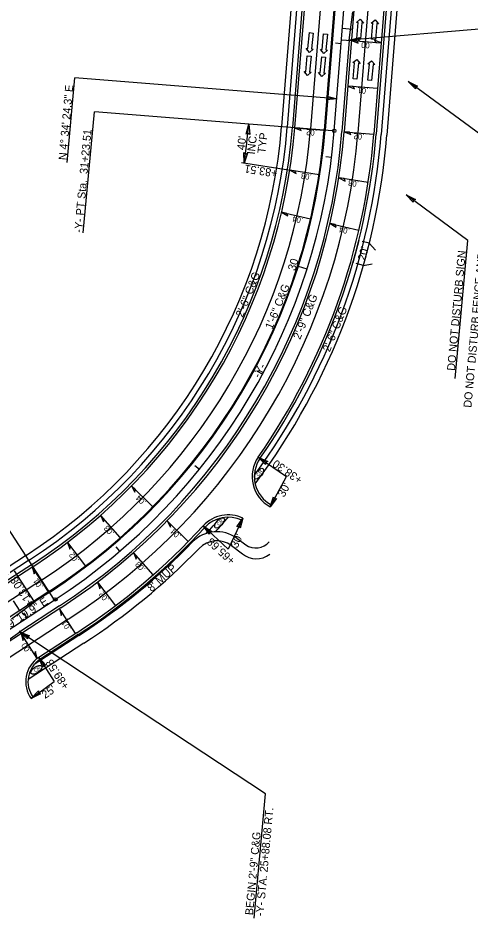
# Model space of a CAD drawing. Extents: x 2010838 to 2015151, y 441905 to 447792.
# Drawn here: x 2012349 to 2012745, y 445665 to 446452 of the extents above; entities that cross this region are included whole.
import ezdxf

# ---------------------------------------------------------------- set-up
doc = ezdxf.new("R2010")
doc.units = 0
for name, color, linetype in [('A-Wall-Abov', 7, 'Continuous'), ('A-Wall-Blow', 7, 'Continuous'), ('A-Wall-Comp', 7, 'Continuous'), ('B-Sheet Number', 7, 'Continuous'), ('C-Building', 7, 'Continuous'), ('C-EOP 1', 7, 'Continuous'), ('C-Grave Plots', 7, 'Continuous'), ('C-Profile', 7, 'Continuous'), ('C-SHBD-TEXT', 7, 'Continuous'), ('CLRD', 7, 'Continuous'), ('Cont-2-Lidar', 7, 'Continuous'), ('DEED', 7, 'Continuous'), ('Default_10ft_LIDAR_Contou', 7, 'Continuous'), ('Default_2FT_LIDAR_Contour', 7, 'Continuous'), ('HATCH', 7, 'Continuous'), ('s-Existing Major', 7, 'Continuous'), ('S-Existing Minor', 7, 'Continuous'), ('S-overhead electric', 7, 'Continuous'), ('TEXT-LG', 7, 'Continuous'), ('TEXT-MED', 7, 'Continuous'), ('X2', 7, 'Continuous'), ('X4', 7, 'Continuous')]:
    doc.layers.add(name, color=color, linetype=linetype)

msp = doc.modelspace()

# ---------------------------------------------------------------- linework, layer by layer
at = {"layer": 'A-Wall-Abov'}
for p, q in [((2012645.07, 446448.16), (2012648.42, 446451.05)), ((2012648.42, 446451.05), (2012651.35, 446447.64)), ((2012658.07, 446447.62), (2012661.42, 446450.5)), ((2012661.42, 446450.5), (2012664.35, 446447.09)), ((2012646.56, 446448.04), (2012645.07, 446448.16)), ((2012645.41, 446434.09), (2012646.56, 446448.04)), ((2012649.85, 446447.77), (2012648.69, 446433.82)), ((2012651.35, 446447.64), (2012649.85, 446447.77)), ((2012659.57, 446447.49), (2012658.07, 446447.62)), ((2012658.41, 446433.54), (2012659.57, 446447.49)), ((2012662.86, 446447.22), (2012661.7, 446433.27)), ((2012664.35, 446447.09), (2012662.86, 446447.22)), ((2012602.65, 446425.34), (2012603.97, 446439.28)), ((2012603.97, 446439.28), (2012607.25, 446438.97)), ((2012607.25, 446438.97), (2012605.93, 446425.03)), ((2012615.15, 446424.44), (2012616.47, 446438.38)), ((2012616.47, 446438.38), (2012619.75, 446438.07)), ((2012619.75, 446438.07), (2012618.43, 446424.13)), ((2012648.69, 446433.82), (2012645.41, 446434.09)), ((2012661.7, 446433.27), (2012658.41, 446433.54)), ((2012600.8, 446405.03), (2012602.13, 446418.97)), ((2012604.04, 446422.05), (2012601.15, 446425.48)), ((2012601.15, 446425.48), (2012602.65, 446425.34)), ((2012602.13, 446418.97), (2012605.41, 446418.66)), ((2012607.43, 446424.89), (2012604.04, 446422.05)), ((2012605.41, 446418.66), (2012604.09, 446404.72)), ((2012605.93, 446425.03), (2012607.43, 446424.89)), ((2012616.54, 446421.15), (2012613.65, 446424.59)), ((2012613.65, 446424.59), (2012615.15, 446424.44)), ((2012619.92, 446423.99), (2012616.54, 446421.15)), ((2012618.43, 446424.13), (2012619.92, 446423.99)), ((2012613.42, 446404.18), (2012614.74, 446418.12)), ((2012614.74, 446418.12), (2012618.03, 446417.81)), ((2012618.03, 446417.81), (2012616.71, 446403.87)), ((2012642.07, 446413.04), (2012645.45, 446415.88)), ((2012643.56, 446412.9), (2012642.07, 446413.04)), ((2012642.24, 446398.96), (2012643.56, 446412.9)), ((2012645.45, 446415.88), (2012648.34, 446412.44)), ((2012646.85, 446412.58), (2012645.53, 446398.65)), ((2012648.34, 446412.44), (2012646.85, 446412.58)), ((2012654.99, 446411.93), (2012658.37, 446414.77)), ((2012656.48, 446411.79), (2012654.99, 446411.93)), ((2012655.16, 446397.85), (2012656.48, 446411.79)), ((2012658.37, 446414.77), (2012661.26, 446411.34)), ((2012659.77, 446411.48), (2012658.45, 446397.54)), ((2012661.26, 446411.34), (2012659.77, 446411.48)), ((2012602.2, 446401.73), (2012599.31, 446405.17)), ((2012599.31, 446405.17), (2012600.8, 446405.03)), ((2012605.58, 446404.58), (2012602.2, 446401.73)), ((2012604.09, 446404.72), (2012605.58, 446404.58)), ((2012614.82, 446400.88), (2012611.93, 446404.32)), ((2012611.93, 446404.32), (2012613.42, 446404.18)), ((2012618.2, 446403.73), (2012614.82, 446400.88)), ((2012616.71, 446403.87), (2012618.2, 446403.73)), ((2012645.53, 446398.65), (2012642.24, 446398.96)), ((2012658.45, 446397.54), (2012655.16, 446397.85))]:
    msp.add_line(p, q, dxfattribs=at)
at = {"layer": 'A-Wall-Blow'}
for p, q in [((2012640.84, 446432.42), (2012666.76, 446430.34)), ((2012663.57, 446390.47), (2012637.65, 446392.54)), ((2012591.1, 446356.14), (2012617.02, 446354.07)), ((2012634.47, 446352.67), (2012660.38, 446350.6)), ((2012612.43, 446314.99), (2012586.74, 446318.98)), ((2012655.42, 446308.32), (2012629.73, 446312.31)), ((2012579.64, 446282.24), (2012604.97, 446276.36)), ((2012622.02, 446272.41), (2012647.34, 446266.53)), ((2012448.4, 446042.87), (2012466.98, 446024.68)), ((2012438.42, 445997.61), (2012421.25, 446017.13)), ((2012479.48, 446012.43), (2012498.05, 445994.24)), ((2012392.26, 445993.47), (2012407.95, 445972.73)), ((2012467.16, 445964.96), (2012449.98, 445984.47)), ((2012375.69, 445950.16), (2012361.53, 445971.97)), ((2012418.5, 445958.77), (2012434.19, 445938.04)), ((2012399.36, 445913.73), (2012385.23, 445935.49)), ((2012365.87, 445891.86), (2012351.68, 445913.7))]:
    msp.add_line(p, q, dxfattribs=at)
at = {"layer": 'A-Wall-Comp'}
for points in [[(2012640.84, 446432.42), (2012646.67, 446429.94), (2012645.45, 446432.05)], [(2012666.76, 446430.34), (2012660.94, 446432.81), (2012662.15, 446430.71)], [(2012637.65, 446392.54), (2012643.48, 446390.07), (2012642.27, 446392.17)], [(2012591.1, 446356.14), (2012596.93, 446353.67), (2012595.71, 446355.77)], [(2012634.47, 446352.67), (2012640.29, 446350.2), (2012639.08, 446352.3)], [(2012586.74, 446318.98), (2012592.36, 446316.08), (2012591.31, 446318.27)], [(2012629.73, 446312.31), (2012635.35, 446309.41), (2012634.3, 446311.6)], [(2012579.64, 446282.24), (2012585.03, 446278.94), (2012584.15, 446281.19)], [(2012622.02, 446272.41), (2012627.41, 446269.1), (2012626.52, 446271.36)], [(2012448.4, 446042.87), (2012451.29, 446037.24), (2012451.71, 446039.64)], [(2012421.25, 446017.13), (2012423.71, 446011.3), (2012424.3, 446013.66)], [(2012479.48, 446012.43), (2012482.36, 446006.81), (2012482.78, 446009.2)], [(2012392.26, 445993.47), (2012394.29, 445987.48), (2012395.05, 445989.78)], [(2012449.98, 445984.47), (2012452.45, 445978.65), (2012453.04, 445981)], [(2012361.53, 445971.97), (2012363.12, 445965.84), (2012364.05, 445968.09)], [(2012418.5, 445958.77), (2012420.53, 445952.78), (2012421.29, 445955.09)], [(2012385.23, 445935.49), (2012386.82, 445929.37), (2012387.75, 445931.61)], [(2012351.68, 445913.7), (2012353.28, 445907.57), (2012354.2, 445909.82)], [(2012365.87, 445891.86), (2012364.28, 445897.98), (2012363.35, 445895.73)]]:
    msp.add_lwpolyline(points, close=True, dxfattribs=at)
at = {"layer": 'B-Sheet Number'}
for p, q in [((2012656.42, 446255.07), (2012650.05, 446256.65)), ((2012651.2, 446235.53), (2012644.89, 446237.33))]:
    msp.add_line(p, q, dxfattribs=at)
at = {"layer": 'C-Building'}
for p, q in [((2012631.84, 446429.61), (2012626.86, 446430.01)), ((2012623.36, 446329.98), (2012618.4, 446330.6)), ((2012562.97, 446140.51), (2012558.57, 446142.88)), ((2012507.72, 446057.33), (2012503.83, 446060.47)), ((2012438.1, 445985.75), (2012434.85, 445989.55)), ((2012356.91, 445927.53), (2012354.19, 445931.72))]:
    msp.add_line(p, q, dxfattribs=at)
at = {"layer": 'C-EOP 1'}
msp.add_line((2012601.96, 446232.44), (2012594.34, 446234.87), dxfattribs=at)
at = {"layer": 'C-Profile'}
for p, q in [((2012638.85, 446432.58), (2012642.09, 446457.4)), ((2012638.85, 446432.58), (2012632.47, 446352.83)), ((2012343.24, 445926.69), (2012363.52, 445941.36)), ((2012385.33, 445937.94), (2012350.6, 445915.37)), ((2012330.31, 445900.7), (2012350.6, 445915.37))]:
    msp.add_line(p, q, dxfattribs=at)
msp.add_arc((2012087.46, 446396.43), 546.75, 303.01114, 355.42659, dxfattribs=at)
at = {"layer": 'C-SHBD-TEXT'}
for p, q in [((2012632.92, 446443.08), (2012641.64, 446442.38)), ((2012632.12, 446433.11), (2012640.84, 446432.42)), ((2012350.94, 445933.19), (2012344.95, 445942.41)), ((2012356.18, 445906.78), (2012350.19, 445916))]:
    msp.add_line(p, q, dxfattribs=at)
at = {"layer": 'CLRD'}
for p, q in [((2012625.74, 446353.37), (2012648.26, 446634.86)), ((2012312.18, 445898.46), (2012381.66, 445943.6))]:
    msp.add_line(p, q, dxfattribs=at)
msp.add_arc((2012087.46, 446396.43), 540, 303.01114, 355.42659, dxfattribs=at)
at = {"layer": 'DEED'}
for p, q in [((2012636.91, 446593.31), (2012617.77, 446354.01)), ((2012377.3, 445950.31), (2012363.52, 445941.36))]:
    msp.add_line(p, q, dxfattribs=at)
msp.add_arc((2012087.46, 446396.43), 532, 303.01114, 355.42659, dxfattribs=at)
at = {"layer": 'Default_10ft_LIDAR_Contou'}
for p, q in [((2012392.06, 446325.83), (2012398.87, 446399.86)), ((2012628, 446381.53), (2012398.87, 446399.86)), ((2012406.15, 446264.23), (2012415.89, 446370.16)), ((2012624.25, 446353.49), (2012415.89, 446370.16)), ((2012380.73, 445943.63), (2012253.57, 446139.34))]:
    msp.add_line(p, q, dxfattribs=at)
for centre in [(2012625.74, 446353.37), (2012625.74, 446353.37), (2012381.66, 445943.6), (2012381.66, 445943.6)]:
    msp.add_circle(centre, 1.5, dxfattribs=at)
at = {"layer": 'HATCH'}
for p, q in [((2012627.58, 446636.51), (2012605.06, 446355.02)), ((2012668.94, 446633.2), (2012646.43, 446351.71)), ((2012370.35, 445961), (2012300.87, 445915.86)), ((2012392.96, 445926.2), (2012323.48, 445881.06))]:
    msp.add_line(p, q, dxfattribs=at)
for radius in [519.25, 560.75]:
    msp.add_arc((2012087.46, 446396.43), radius, 303.01114, 355.42659, dxfattribs=at)
at = {"layer": 's-Existing Major'}
for points in [[(2012647.95, 446431.81), (2012638.85, 446432.58), (2012647.73, 446434.95), (2012646.72, 446433.26)], [(2012696.8, 446390.03), (2012690.47, 446396.61), (2012698.71, 446392.54), (2012696.84, 446391.93)], [(2012619.15, 446383.79), (2012628, 446381.53), (2012618.85, 446380.66), (2012620.12, 446382.16)], [(2012548.6, 446350.51), (2012550.86, 446359.36), (2012551.73, 446350.21), (2012550.23, 446351.48)], [(2012549.76, 446333.82), (2012546.85, 446325.17), (2012546.65, 446334.35), (2012548.06, 446332.97)], [(2012694.88, 446290.93), (2012688.56, 446297.53), (2012696.79, 446293.44), (2012694.91, 446292.83)], [(2012565.72, 446061.71), (2012559.22, 446068.12), (2012567.56, 446064.26), (2012565.7, 446063.61)], [(2012575.32, 446031.73), (2012569.71, 446024.52), (2012572.56, 446033.25), (2012573.43, 446031.49)], [(2012540.62, 446007.2), (2012545.86, 446014.67), (2012543.44, 446005.81), (2012542.49, 446007.53)], [(2012516.52, 446000.61), (2012510.94, 446007.83), (2012518.69, 446002.89), (2012516.76, 446002.49)], [(2012357.25, 445909.12), (2012350.6, 445915.37), (2012359.03, 445911.72), (2012357.19, 445911.02)], [(2012370.71, 445884.32), (2012367.1, 445892.71), (2012373.38, 445885.99), (2012371.41, 445886.08)], [(2012368.74, 445861.02), (2012360.57, 445856.94), (2012366.92, 445863.59), (2012366.94, 445861.62)]]:
    msp.add_lwpolyline(points, close=True, dxfattribs=at)
at = {"layer": 'S-Existing Minor'}
for p, q in [((2012849.28, 446450.8), (2012638.85, 446432.58)), ((2012767.58, 446339.91), (2012690.47, 446396.61)), ((2012585.69, 446319.14), (2012544.71, 446325.5)), ((2012742.63, 446257.55), (2012688.56, 446297.53)), ((2012731.53, 446136.8), (2012742.63, 446257.55)), ((2012559.22, 446068.12), (2012583.84, 446050.98)), ((2012569.71, 446024.52), (2012583.84, 446050.98)), ((2012545.86, 446014.67), (2012533.04, 445987.55)), ((2012510.94, 446007.83), (2012533.04, 445987.55)), ((2012363.52, 445941.36), (2012345.92, 445968.45)), ((2012565.55, 445773.54), (2012350.6, 445915.37)), ((2012367.1, 445892.71), (2012380.72, 445871.74)), ((2012360.57, 445856.94), (2012380.72, 445871.74)), ((2012555.57, 445664.94), (2012565.55, 445773.54))]:
    msp.add_line(p, q, dxfattribs=at)
msp.add_arc((2012087.46, 446396.43), 464.88, 351.18238, 355.42659, dxfattribs=at)
at = {"layer": 'S-overhead electric'}
for p, q in [((2012682.9, 446632.09), (2012660.38, 446350.6)), ((2012611.86, 446615.65), (2012591.1, 446356.14)), ((2012636.16, 446593.37), (2012617.02, 446354.07)), ((2012649.62, 446542.13), (2012634.47, 446352.67)), ((2012656.42, 446255.07), (2012661.88, 446249.18)), ((2012651.2, 446235.53), (2012658.83, 446236.95)), ((2012362.72, 445972.74), (2012293.25, 445927.6)), ((2012376.89, 445950.94), (2012307.41, 445905.8)), ((2012386.42, 445936.26), (2012316.95, 445891.13)), ((2012400.59, 445914.46), (2012367.1, 445892.71))]:
    msp.add_line(p, q, dxfattribs=at)
for centre, radius, start, end in [((2012087.46, 446396.43), 505.25, 303.01114, 355.42659), ((2012087.46, 446396.43), 531.25, 303.01114, 355.42659), ((2012087.46, 446396.43), 548.75, 303.01114, 355.42659), ((2012087.46, 446396.43), 574.75, 325.16479, 355.42659), ((2012583.84, 446050.98), 30, 145.16479, 241.9049), ((2012533.04, 445987.55), 30, 64.70104, 137.45962), ((2012087.46, 446396.43), 574.75, 303.01114, 317.45962), ((2012380.72, 445871.74), 25, 123.01114, 216.29419)]:
    msp.add_arc(centre, radius, start, end, dxfattribs=at)
at = {"layer": 'TEXT-LG'}
for p, q in [((2012601.76, 446633.53), (2012579.64, 446357.06)), ((2012689.38, 446631.57), (2012666.86, 446350.08)), ((2012694.36, 446631.17), (2012671.85, 446349.68)), ((2012606.39, 446628.77), (2012584.62, 446356.66)), ((2012540.4, 445997.07), (2012548.31, 445991.28)), ((2012535.68, 445990.61), (2012545.36, 445983.53)), ((2012356.46, 445982.39), (2012286.98, 445937.25)), ((2012359.18, 445978.19), (2012289.71, 445933.05)), ((2012402.22, 445911.95), (2012363.11, 445886.54)), ((2012406.58, 445905.24), (2012357.79, 445873.54))]:
    msp.add_line(p, q, dxfattribs=at)
for centre, radius, start, end in [((2012087.46, 446396.43), 493.75, 303.01114, 355.42659), ((2012087.46, 446396.43), 498.75, 303.01114, 355.42659), ((2012087.46, 446396.43), 581.25, 323.69358, 355.42659), ((2012087.46, 446396.43), 586.25, 323.14222, 355.42659), ((2012087.46, 446396.43), 581.25, 317.16838, 318.93083), ((2012087.46, 446396.43), 586.25, 317.81387, 319.48219), ((2012522.99, 445973.26), 29.5, 53.81366, 135.82423), ((2012087.46, 446396.43), 577.75, 303.01114, 315.82423), ((2012522.99, 445973.26), 21.5, 53.81366, 135.82423), ((2012557.07, 446003.92), 15.38, 235.26505, 319.35318), ((2012087.46, 446396.43), 585.75, 303.01114, 315.82423), ((2012557.48, 445997.56), 18.55, 229.18865, 309.31059)]:
    msp.add_arc(centre, radius, start, end, dxfattribs=at)
at = {"layer": 'TEXT-MED'}
for p, q in [((2012684.89, 446631.93), (2012662.38, 446350.44)), ((2012609.87, 446615.81), (2012589.11, 446356.3)), ((2012361.63, 445974.42), (2012292.16, 445929.28)), ((2012401.68, 445912.78), (2012368.19, 445891.03))]:
    msp.add_line(p, q, dxfattribs=at)
for centre, radius, start, end in [((2012087.46, 446396.43), 503.25, 303.01114, 355.42659), ((2012087.46, 446396.43), 576.75, 325.14232, 355.42659), ((2012583.84, 446050.98), 28, 145.16479, 241.9049), ((2012533.04, 445987.55), 28, 64.70104, 137.45962), ((2012087.46, 446396.43), 576.75, 303.01114, 317.45962), ((2012380.72, 445871.74), 23, 123.01114, 216.29419)]:
    msp.add_arc(centre, radius, start, end, dxfattribs=at)
at = {"layer": 'X2'}
msp.add_line((2012647.15, 446257.43), (2012641.99, 446238.1), dxfattribs=at)
at = {"layer": 'X4'}
for centre, major_axis in [((2012559.9, 446053.56), (3.42, 4.44)), ((2012525.41, 446010.45), (3.79, 4.14)), ((2012365.17, 445882.08), (4.59, 3.22))]:
    msp.add_ellipse(centre, major_axis=major_axis, ratio=0.462467, dxfattribs=at)

# ---------------------------------------------------------------- texts
at = {"layer": 'A-Wall-Blow'}
for s, rotation, p in [('.00', 175.42659, (2012658.8, 446430.28)), ('.01', 175.42659, (2012655.55, 446390.68)), ('.02', 175.42659, (2012610.63, 446353.97)), ('.02', 175.42659, (2012652.08, 446350.51)), ('.03', 171.18238, (2012606.23, 446315.19)), ('.03', 171.18238, (2012647.54, 446309.02)), ('.04', 166.93825, (2012598.81, 446276.98)), ('.04', 166.93825, (2012639.64, 446267.7)), ('.04', 135.59215, (2012461.69, 446028.72)), ('.03', 131.34802, (2012433.53, 446001.75)), ('.04', 135.59215, (2012492.04, 445999.4)), ('.02', 127.10389, (2012402.82, 445977.9)), ('.03', 131.34802, (2012460.93, 445970.27)), ('.01', 123.01114, (2012371.12, 445954.79)), ('.02', 127.10389, (2012428.92, 445943.52)), ('.01', 123.01114, (2012395.81, 445918.07)), ('.00', 123.01114, (2012360.76, 445898.38))]:
    msp.add_text(s, height=5, rotation=rotation, dxfattribs=at).set_placement(p)
at = {"layer": 'C-Grave Plots'}
for s, rotation, p in [("40'", 83.30449, (2012547.41, 446336.27)), ('INC. ', 83.30449, (2012556.13, 446332.5)), ('TYP', 83.30449, (2012565.39, 446333.32)), ('+83.51', 171.18238, (2012576.38, 446319.42)), ("20'", 75.05521, (2012652.86, 446239.25)), ('2\'-6" C&G', 68.0422, (2012545.64, 446189.79)), ('1\'-6" C&G', 68.0422, (2012571.42, 446179.27)), ('2\'-9" C&G', 68.0422, (2012595.84, 446170.38)), ('2\'-6" C&G', 68.0422, (2012621.78, 446159.55)), ('+38.30', 145.12985, (2012598.6, 446049.74)), ("30'", 61.9049, (2012581.92, 446032.48)), ("30'", 64.70104, (2012540.95, 445987.89)), ('+65.68', 137.40061, (2012539.63, 445978.49)), ("8' MUP", 41.98904, (2012465.89, 445949.76)), ('+13.08', 123.01114, (2012363.26, 445940.23)), ('+89.58', 123.01114, (2012394.24, 445867.81)), ("25'", 35.06365, (2012372.74, 445856.37))]:
    msp.add_text(s, height=7, rotation=rotation, dxfattribs=at).set_placement(p)
at = {"layer": 'Cont-2-Lidar'}
for s, rotation, p in [('N 4%%d 34\' 24.3" E', 84.74666, (2012391.35, 446327.52)), ('N 56%%d 59\' 19.9" E', 33.01114, (2012316.27, 445901.36))]:
    msp.add_text(s, height=7, rotation=rotation, dxfattribs=at).set_placement(p)
at = {"layer": 'Default_10ft_LIDAR_Contou'}
msp.add_text('-Y- PT Sta.  31+23.51', height=7, rotation=84.74666, dxfattribs=at).set_placement((2012405.12, 446264.13))
at = {"layer": 'Default_2FT_LIDAR_Contour'}
for s, rotation, p in [('30', 72.32164, (2012591.49, 446230.46)), ('-Y-', 62.26996, (2012560.43, 446136.63))]:
    msp.add_text(s, height=7, rotation=rotation, dxfattribs=at).set_placement(p)
at = {"layer": 'S-Existing Minor'}
for s, p in [('DO NOT DISTURB FENCE AND RETAINING WALL', (2012745.71, 446111.02)), ('DO NOT DISTURB SIGN', (2012731.31, 446143.32)), ('-Y- STA. 25+88.08 RT.', (2012563.79, 445666.34)), ('BEGIN 2\'-9" C&G ', (2012554.65, 445667.18))]:
    msp.add_text(s, height=7, rotation=84.74666, dxfattribs=at).set_placement(p)
at = {"layer": 'X4'}
for rotation, p in [(52.44013, (2012559.63, 446050.79)), (47.53785, (2012524.9, 446007.72)), (35.0058, (2012364.09, 445879.52))]:
    msp.add_text('CR', height=3, rotation=rotation, dxfattribs=at).set_placement(p)

doc.saveas('drawing.dxf')
